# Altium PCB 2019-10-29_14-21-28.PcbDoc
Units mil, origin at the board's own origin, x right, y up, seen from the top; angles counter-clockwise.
Board outline 2004 x 2504 mil, 4 copper layers (Top Layer, MidLayer1, MidLayer2, Bottom Layer); 21 components, 11 nets, 42 pads, 203 vias.
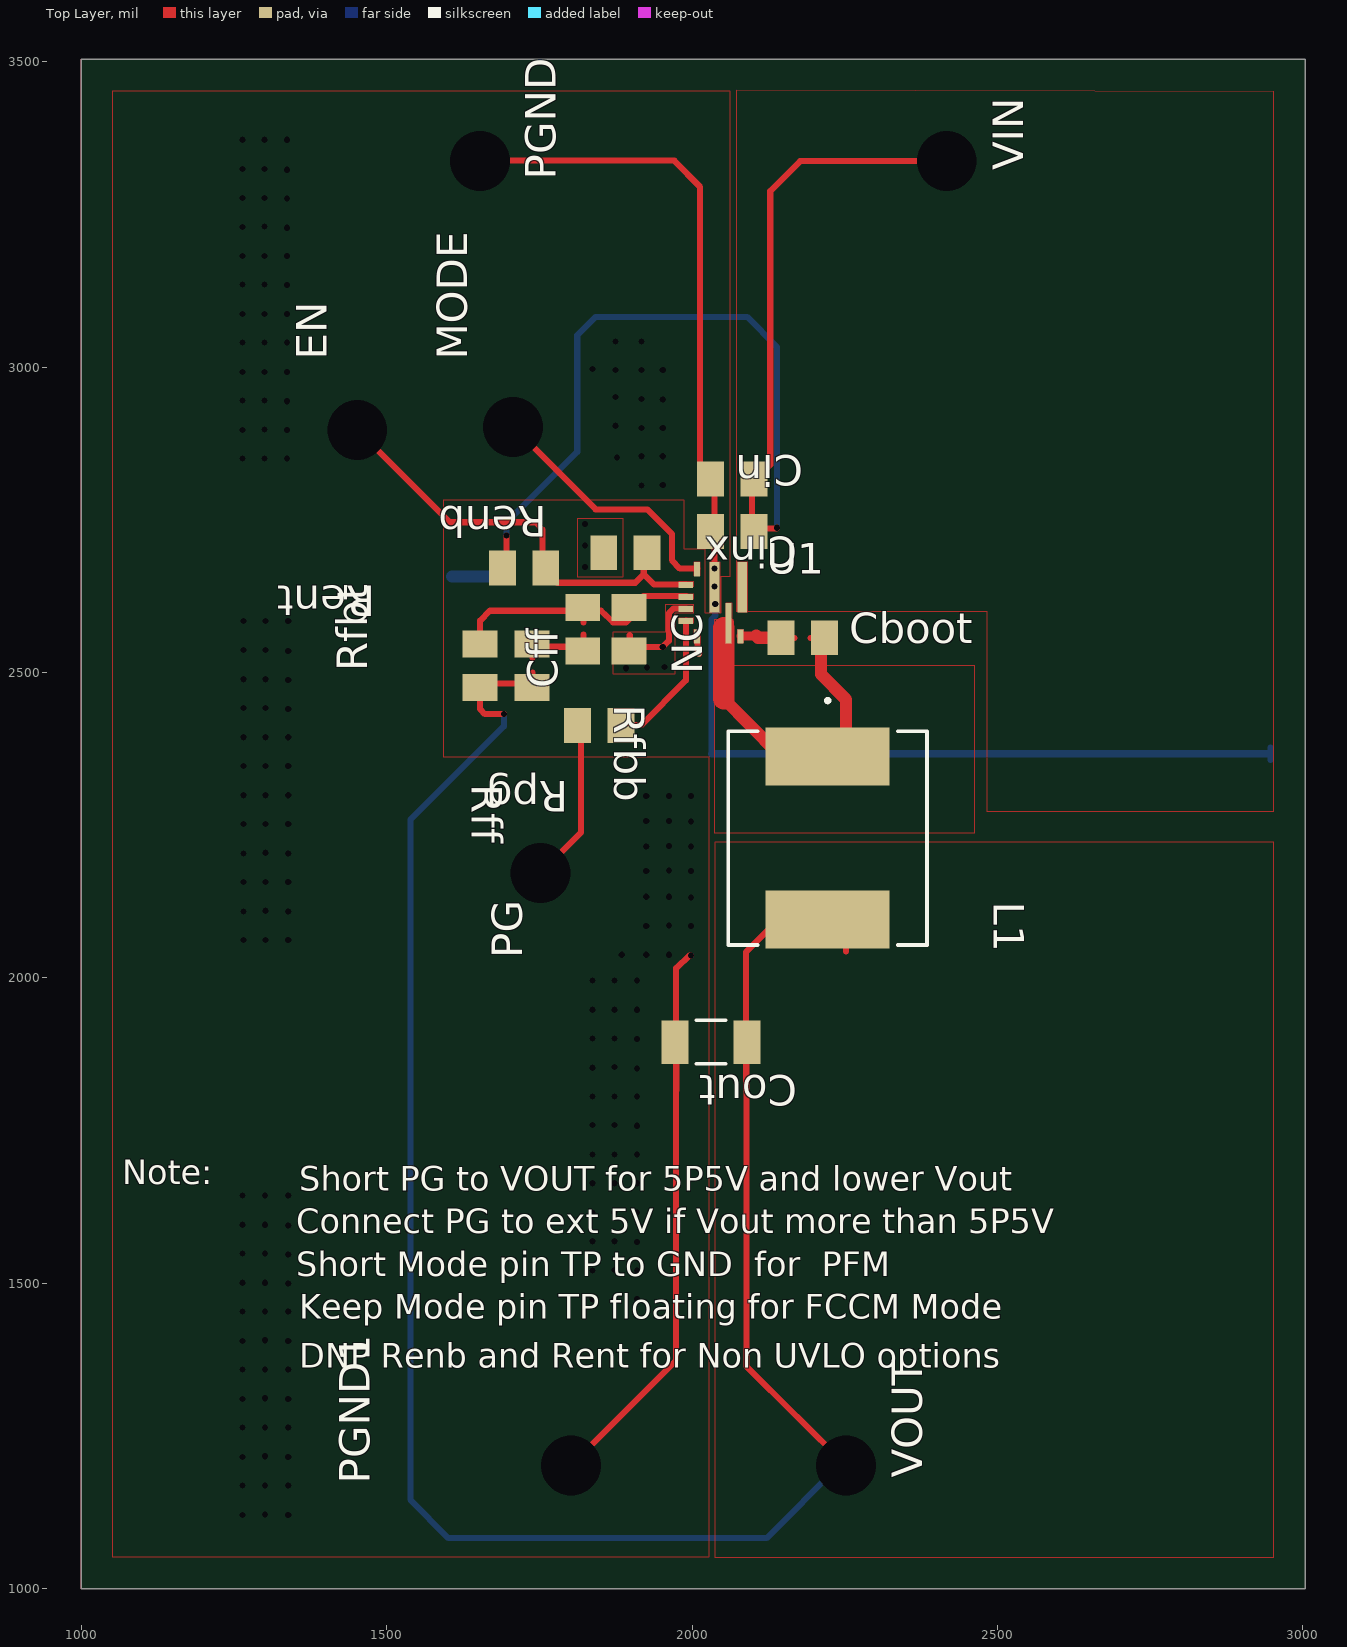
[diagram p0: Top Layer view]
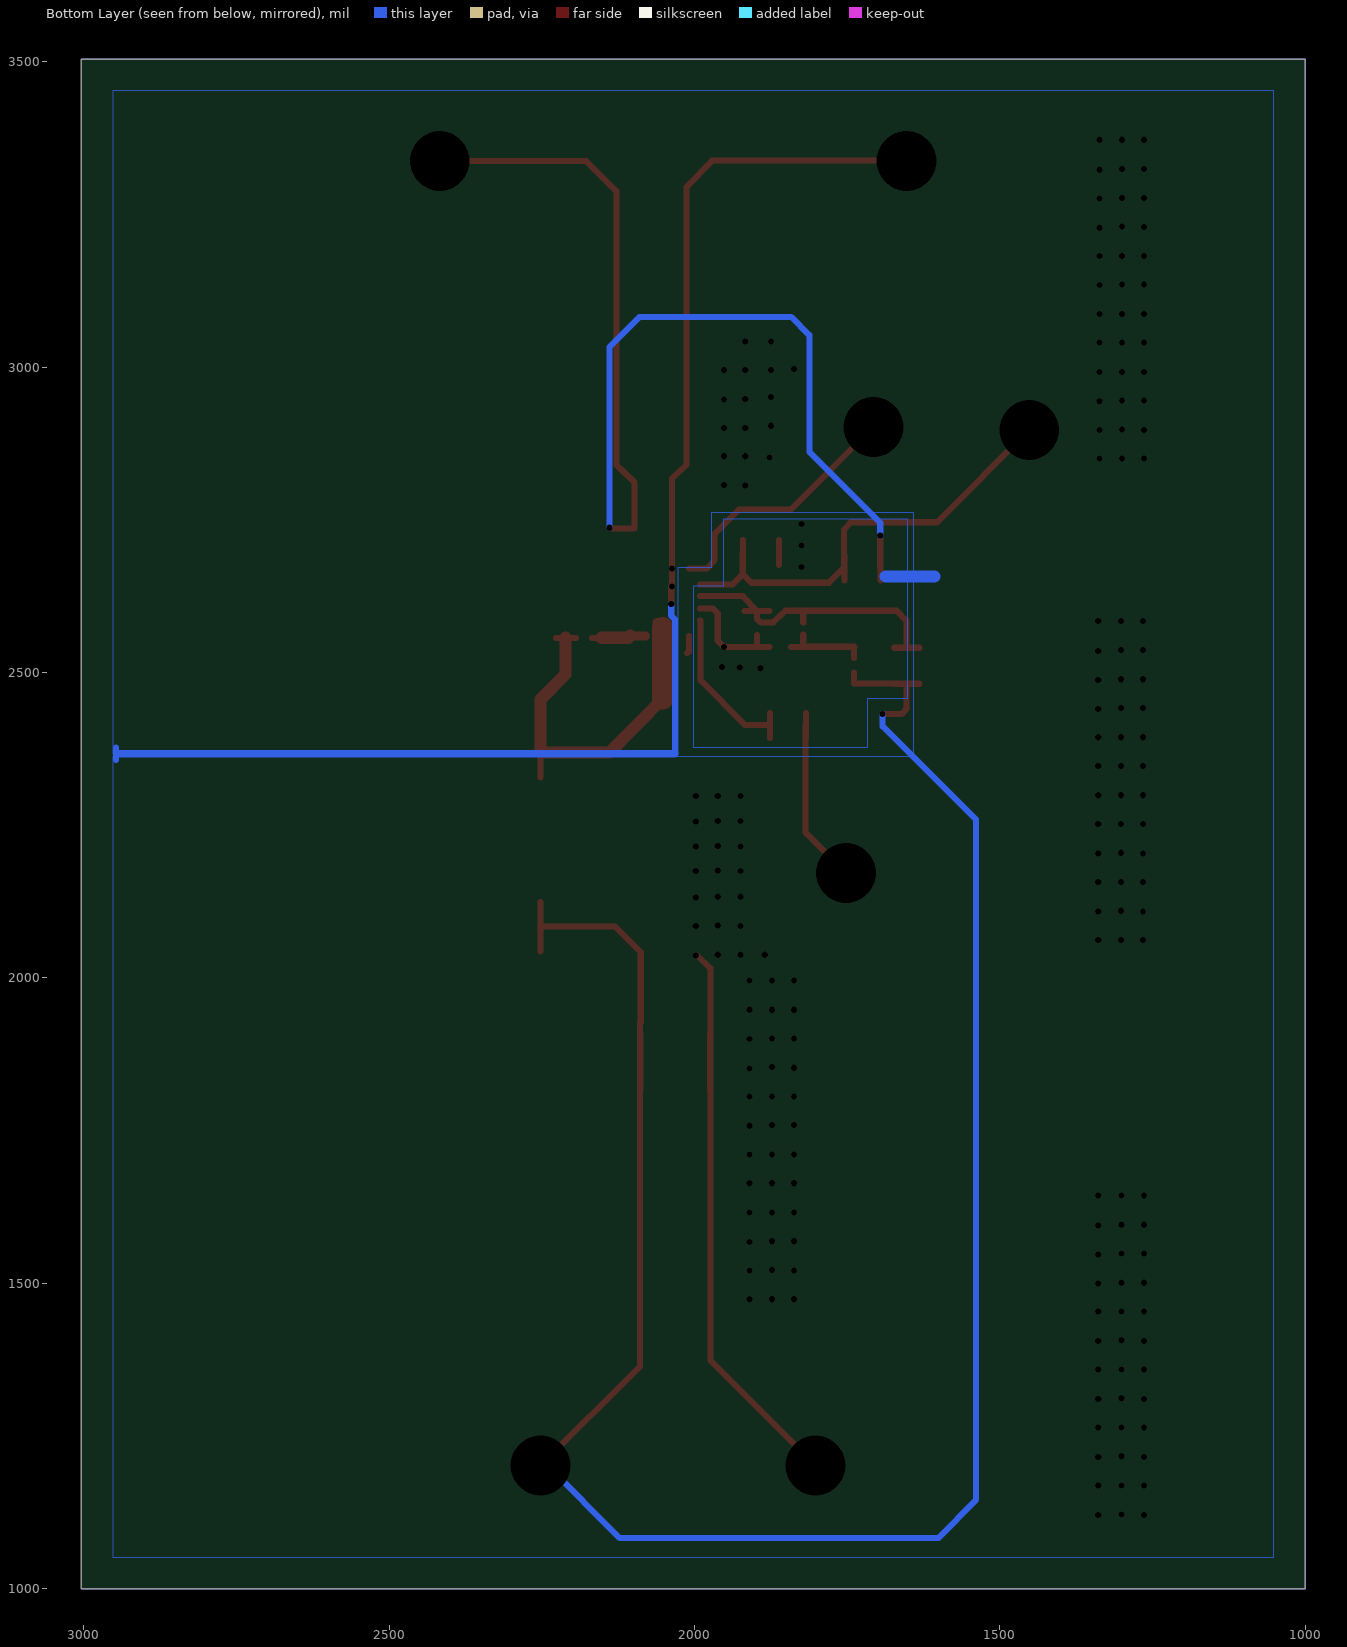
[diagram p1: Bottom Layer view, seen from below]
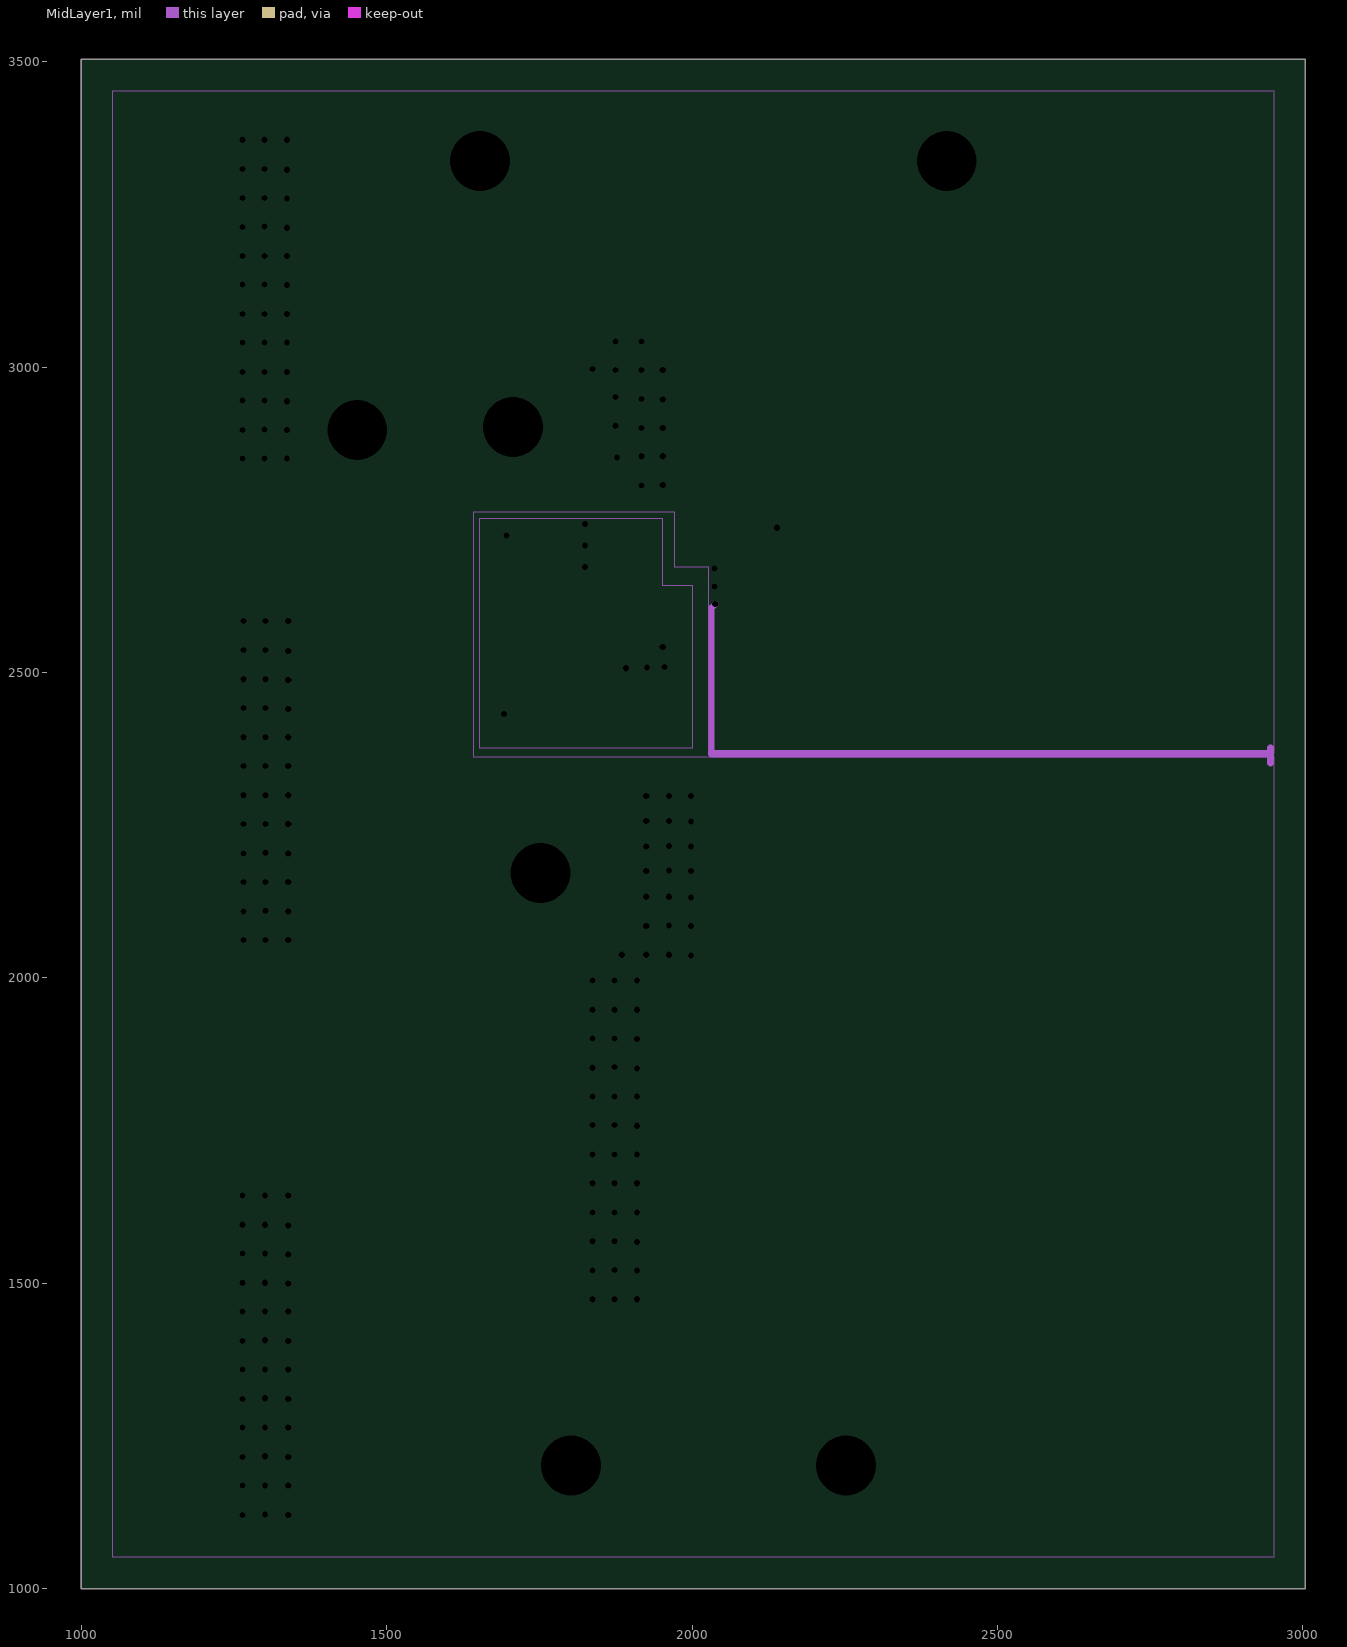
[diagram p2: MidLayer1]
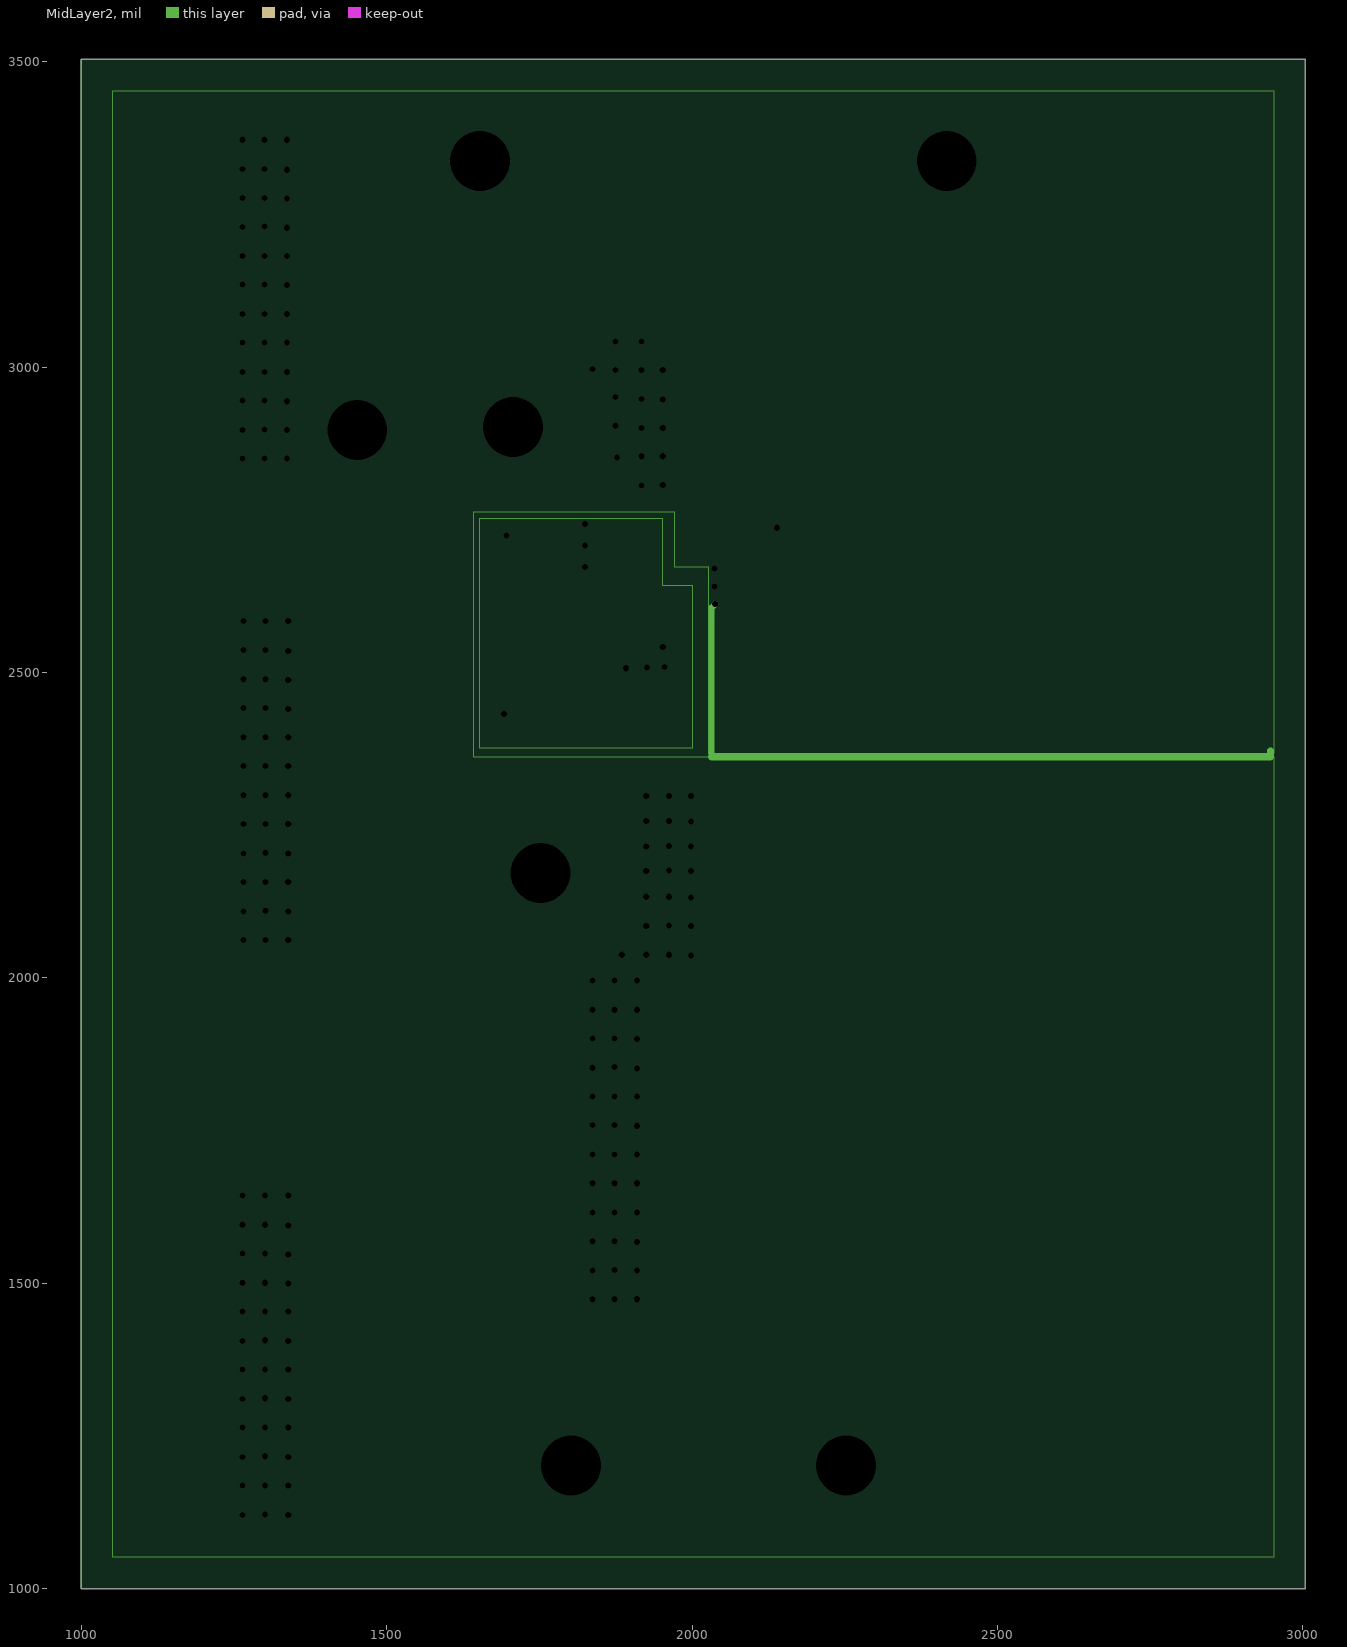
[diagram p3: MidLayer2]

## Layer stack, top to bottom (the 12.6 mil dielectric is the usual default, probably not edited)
Top Layer: signal copper 1.4
Dielectric: core 12.6, FR-4, Dk 4.8
MidLayer1: signal copper 1.4
Dielectric: prepreg 12.6, FR-4, Dk 4.8
MidLayer2: signal copper 1.4
Dielectric: core 12.6, FR-4, Dk 4.8
Bottom Layer: signal copper 1.4

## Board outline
1000,1000 3004,1000 3004,3504 1000,3504

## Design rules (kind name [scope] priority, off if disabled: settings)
PlaneConnect [All] p0: scope1count=1 scope1_0_kind=Board scope1_0_value=Board scope2count=1 scope2_0_kind=Board scope2_0_value=Board commentlength=0 planeconnectstyle=Direct reliefexpansion=20 reliefentries=4 reliefconductorwidth=10 reliefairgap=10
PlaneConnect [All] p1: planeconnectstyle=Direct reliefexpansion=20 reliefentries=4 reliefconductorwidth=10 reliefairgap=10
PolygonConnect [All] p0: scope1count=1 scope1_0_kind=Board scope1_0_value=Board scope2count=1 scope2_0_kind=Board scope2_0_value=Board commentlength=0 connectstyle=Direct reliefconductorwidth=10 reliefentries=4 polygonreliefangle="90 Angle"
PolygonConnect [All] p1: connectstyle=Direct reliefconductorwidth=10 reliefentries=4 polygonreliefangle="90 Angle"

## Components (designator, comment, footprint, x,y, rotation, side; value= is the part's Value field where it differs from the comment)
Cboot "" 0805 2181,2557 r0 top
Cff "" 0805 1821,2571 r90 top
Cin "" 0805 2066,2817 r180 top
Cinx "" 0805 2066,2731 r180 top
Cout "" 1206_190 2031,1895 r180 top
EN "" TP-1502 1451,2896 r90 top
L1 "" IHLP-3232DZ 2222,2229 r270 top
MODE "" TP-1502 1706,2901 r90 top
NC "" SMD_PAD1 2011,2531 r90 top
PG "" TP-1502 1751,2171 r90 top
PGND "" TP-1502 1653,3336 r90 top
PGND1 "" TP-1502 1801,1201 r90 top
Renb "" 0805 1891,2696 r180 top
Rent "" 0805 1725,2671 r180 top
Rfbb "" 0805 1897,2571 r270 top
Rfbt "" 0805 1653,2511 r90 top
Rff "" 0805 1738,2511 r270 top
Rpg "" 0805 1848,2413 r180 top
U1 "" RPA0010A 2045,2614 r0 top
VIN "" TP-1502 2416,3336 r90 top
VOUT "" TP-1502 2251,1201 r90 top

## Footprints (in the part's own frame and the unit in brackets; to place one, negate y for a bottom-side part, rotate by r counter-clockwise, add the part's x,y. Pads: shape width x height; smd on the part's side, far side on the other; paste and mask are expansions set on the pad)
0805 [mil]
  rect 44x57 smd: 1(-35.5,0) 2(35.5,0)
1206_190 [mil]
  rect 44x71 smd: 1(-59,0) 2(59,0)
  silkscreen extent -24,-36 24,36
IHLP-3232DZ [mil]
  rect 95x203 smd: 1(-133.5,0) 2(133.5,0)
  silkscreen extent -228,-163 175,163
RPA0010A [mm]
  rect 0.6x0.25 smd: 1(-1.4,0.75) 2(-1.4,0.25) 3(-1.4,-0.25) 4(-1.4,-0.75)
  rect 0.25x0.6 smd: 5(-0.93,-1.4) 7(0.87,-1.4) 10(-0.93,1.4)
  rect 0.25x1.7 smd: 6(0.37,-0.85)
  rect 0.4x2.1 smd: 8(0.95,0.65) 9(-0.21,0.65)
SMD_PAD1 [mil]
  round 10 smd: 1(0,0)
TP-1502 [mil]
  round 65 / inner round 0 / far side round 65 hole 32: 1(0,0)

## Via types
v1: diameter 0, hole 10, Top Layer to Bottom Layer, 196 vias
v2: diameter 0, hole 98, Top Layer to Bottom Layer, 7 vias

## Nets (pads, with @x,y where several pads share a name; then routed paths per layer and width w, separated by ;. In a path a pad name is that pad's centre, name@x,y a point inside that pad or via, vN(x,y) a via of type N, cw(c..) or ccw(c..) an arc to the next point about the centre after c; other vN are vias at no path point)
0: Cin.2 Cinx.2 Cout.2 PGND1.1 PGND.1 Renb.2 Rfbb.2 U1.3 U1.9 | length 5945.9
  Top Layer w10: PGND.1@1653,3338 1971,3338 2013,3295 2013,2840 2037,2817 2037,2732 v1(2037,2670) v1(2037,2641) 2038,2641 v1(2038,2612) ; v2(1802,1202) 1974,1374 1974,1862 1974,2016 1996,2037 v1(1998,2037) ; Renb.2@1861.5,2676 Renb.2@1861.5,2717 ; Rfbb.2@1877,2541.5 Rfbb.2@1918,2541.5 ; 1898,2561 1898,2542 v1(1952,2542) 1962,2552 1962,2597 1970,2605 U1.3@1991,2605 ; 1974.5,1816 Cout.2@1974.5,1908
  MidLayer1 w10: 2032,2367 2032,2606 v1(2038,2612)
  MidLayer1 w11: 2947,2352 2947,2377
  MidLayer1 w12: 2032,2367 2942,2367
  MidLayer2 w10: 2032,2362 2032,2606 v1(2038,2612)
  MidLayer2 w11: 2947,2362 2947,2372
  MidLayer2 w12: 2032,2362 2947,2362
  Bottom Layer w10: 2032,2367 2032,2587 2038,2593 v1(2038,2612) ; 2947,2357 2947,2377
  Bottom Layer w12: 2032,2367 2942,2367
  Bottom Layer w20: 1607,2657 1687,2657
  other v1: 1264,1121 1339,1121 1301,1122 1264,1169 1301,1169 1339,1169 1264,1216 1339,1216 1301,1217 1264,1264 1301,1264 1339,1264 1264,1311 1339,1311 1301,1312 1264,1359 1301,1359 1339,1359 1264,1406 1339,1406 1301,1407 1264,1454 1301,1454 1339,1454 1837,1474 1873,1474 1910,1474 1339,1500 1264,1501 1301,1501 1837,1521 1910,1521 1873,1522 1339,1547 1264,1549 1301,1549 1910,1568 1837,1569 1873,1569 1339,1595 1264,1596 1301,1596 1837,1616 1873,1616 1910,1616 1264,1644 1301,1644 1339,1644 1837,1664 1873,1664 1910,1664 1837,1711 1873,1711 1910,1711 1910,1758 1837,1759 1873,1759 1837,1806 1873,1806 1910,1806 1910,1852 1837,1853 1873,1854 1910,1900 1837,1901 1873,1901 1837,1948 1873,1948 1910,1948 1837,1996 1873,1996 1910,1996 1885,2038 1925,2038 1962,2038 1266,2062 1302,2062 1339,2062 1925,2085 1998,2085 1962,2086 1266,2109 1339,2109 1302,2110 1998,2132 1925,2133 1962,2133 1266,2157 1302,2157 1339,2157 1925,2175 1998,2175 1962,2176 1266,2204 1339,2204 1302,2205 1925,2215 1998,2215 1962,2216 1266,2252 1302,2252 1339,2252 1998,2256 1925,2257 1962,2257 1925,2298 1962,2298 1998,2298 1266,2299 1302,2299 1339,2299 1266,2347 1302,2347 1339,2347 1266,2394 1302,2394 1339,2394 1339,2440 1266,2442 1302,2442 1339,2488 1266,2489 1302,2489 1892,2507 1926,2508 1955,2509 1339,2535 1266,2537 1302,2537 1266,2584 1302,2584 1339,2584 1825,2673 1825,2708 1825,2743 1917,2806 1952,2807 1264,2850 1300,2850 1337,2850 1877,2852 1917,2854 1952,2854 1264,2897 1337,2897 1300,2898 1917,2900 1952,2900 1875,2904 1337,2944 1264,2945 1300,2945 1952,2947 1917,2948 1875,2951 1264,2992 1300,2992 1337,2992 1875,2995 1917,2995 1952,2995 1837,2997 1264,3040 1300,3040 1337,3040 1875,3042 1917,3042 1264,3087 1300,3087 1337,3087 1337,3134 1264,3135 1300,3135 1264,3182 1300,3182 1337,3182 1337,3228 1264,3229 1300,3230 1337,3276 1264,3277 1300,3277 1337,3323 1264,3324 1300,3324 1264,3372 1300,3372 1337,3372
  other v2: 1653,3337
1: Cff.2 Rfbb.1 Rfbt.2 U1.2 | length 563.9
  Top Layer w10: Rfbt.2@1632,2540.5 Rfbt.2@1673,2540.5 ; Rfbt.2@1653,2541 1653,2585 1669,2601 Cff.2@1822,2601 ; Cff.2@1801,2600.5 Cff.2@1842,2600.5 ; 1822,2582 Cff.2@1822,2601 ; Rfbb.1@1877,2600.5 Rfbb.1@1918,2600.5 ; U1.2@1991,2625 1921,2625 1898,2601 1898,2588 1892,2582 1871,2582 1851,2601 Cff.2@1822,2601
2: Cout.1 L1.2 PG.1 Rfbt.1 Rff.2 Rpg.2 VOUT.1 | length 3939.9
  Top Layer w10: Rfbt.1@1632,2481.5 Rfbt.1@1673,2481.5 ; v1(1692,2432) 1661,2432 1653,2440 1653,2482 1739,2482 1739,2500 ; v2(1752,2172) 1818,2238 Rpg.2@1818,2414 ; Rpg.2@1817.5,2393 Rpg.2@1817.5,2434 ; Cout.1@2088,1926 2088,2042 2130,2084 L1.2@2252,2084 ; 2088.5,1816 Cout.1@2088.5,1908 ; Cout.1@2089,1926 2089,1862 2089,1364 v2(2252,1202) ; 2252,2043 L1.2@2252,2124
  Bottom Layer w10: v1(1692,2432) 1692,2412 1539,2259 1539,1146 1601,1083 2122,1083 2241,1202 v2(2252,1202)
3: Cff.1 Rff.1 | length 162
  Top Layer w10: 1739,2524 Rff.1@1739,2541 ; Cff.1@1801,2541.5 Cff.1@1842,2541.5 ; Cff.1@1822,2542 1822,2562
  Top Layer w11: Rff.1@1739,2541 1739,2542 Cff.1@1822,2542
5: Cboot.2 L1.1 U1.6 | length 684.5
  Top Layer w10: 2194,2556.5 Cboot.2@2227,2556.5 ; L1.1@2252,2328 L1.1@2252,2409
  Top Layer w15: 2052,2573 U1.6@2061,2582
  Top Layer w20: 2052,2457 2139,2369 2252,2369 2252,2456 2211,2497 Cboot.2@2211,2557
  Top Layer w35: 2052,2457 2052,2573
6: Cin.1 Cinx.1 Rent.2 U1.8 VIN.1 | length 2040.2
  Top Layer w10: Rent.2@1695.5,2651 Rent.2@1695.5,2692 ; Rent.2@1696,2672 v1(1696,2724) ; v1(2139,2737) 2138,2736 2098,2736 2098,2811 2128,2840 2128,3288 2177,3337 v2(2417,3337)
  Bottom Layer w10: v1(1696,2724) 1696,2745 1812,2861 1812,3052 1842,3082 2090,3082 2139,3033 v1(2139,2737)
10: EN.1 Renb.1 Rent.1 U1.1 | length 810
  Top Layer w10: v2(1452,2897) 1603,2746 1744,2746 1755,2734 1755,2672 1780,2647 1907,2647 1921,2661 ; Rent.1@1754.5,2651 Rent.1@1754.5,2692 ; Renb.1@1920.5,2676 Renb.1@1920.5,2717 ; Renb.1@1921,2697 1921,2661 ; U1.1@1991,2644 1938,2644 1921,2661
16: Cboot.1 U1.7 | length 106.2
  Top Layer w10: Cboot.1@2135,2556.5 2168,2556.5
  Top Layer w15: U1.7@2080,2560 2105,2560
  Top Layer w20: 2105,2560 2108,2557 Cboot.1@2152,2557
17: Rpg.1 U1.4 | length 281.2
  Top Layer w10: Rpg.1@1876.5,2393 Rpg.1@1876.5,2434 ; Rpg.1@1879,2414 1917,2414 1990,2487 1990,2585 U1.4@1991,2585
18: MODE.1 U1.10 | length 423.6
  Top Layer w10: v2(1707,2902) 1842,2767 1927,2767 1967,2727 1967,2684 1980,2670 U1.10@2009,2670
19: NC.1 U1.5 | length 29.6
  Top Layer w10: U1.5@2009,2560 2009,2534 NC.1@2012,2532

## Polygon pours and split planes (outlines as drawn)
10 on Top Layer " " (solid, pour order 0): 1979,2640 1979,2649 2002,2649 2002,2640
1 on Top Layer " " (solid, pour order 1): 1979,2620 1979,2629 2002,2629 2002,2620
17 on Top Layer " " (solid, pour order 2): 1979,2581 1979,2590 2002,2590 2002,2581
19 on Top Layer " " (solid, pour order 3): 2004,2548 2004,2571 2013,2571 2013,2548
5 on Top Layer " " (solid, pour order 4): 2056,2548 2056,2614 2065,2614 2065,2548
16 on Top Layer " " (solid, pour order 5): 2075,2548 2075,2571 2084,2571 2084,2548
6 on Top Layer " " (solid, pour order 6): 2075,2599 2075,2681 2090,2681 2090,2599
18 on Top Layer " " (solid, pour order 7): 2004,2658 2004,2681 2013,2681 2013,2658
19 on Top Layer " " (solid, pour order 8): 2017,2532 2016,2532 2016,2533 2016,2534 2015,2535 2014,2536 2013,2536 2012,2536 2012,2537 2011,2536 2010,2536 2009,2536 2008,2535 2007,2534 2007,2533 2007,2532 2007,2531 2007,2530 2007,2529 2008,2528 2009,2527 2010,2527 2011,2527 2012,2527 2013,2527 2014,2527 2015,2528 2016,2529 2016,2530 2016,2531 2017,2532
6 on Top Layer " " (solid, pour order 9): 2072,3453 2072,2600 2482,2600 2482,2273 2952,2273 2952,3451
2 on Top Layer " " (solid, pour order 10): 2952,2222 2037,2222 2037,1052 2952,1052
5 on Top Layer " " (solid, pour order 11): 2067,2587 2067,2512 2462,2512 2462,2237 2037,2237 2037,2587
0 on Top Layer " " (solid, pour order 12): 1979,2600 1979,2609 2002,2609 2002,2600
0 on Top Layer " " (solid, pour order 13): 2030,2599 2030,2681 2045,2681 2045,2599
0 on Top Layer " " (solid, pour order 20): 2047,2657 2047,2597 2022,2597 2022,2702 1987,2702 1987,2782 1593,2782 1593,2362 2027,2362 2027,1052 1052,1052 1052,3452 2062,3452 2062,2657
0 on Top Layer " " (solid, pour order 21): 1887,2752 1812,2752 1812,2657 1887,2657
0 on Top Layer " " (solid, pour order 22): 1972,2597 1972,2497 1871,2497 1871,2567 1957,2567 1957,2612 2002,2612 2002,2597
0 on Bottom Layer " " (solid, pour order 18): 1652,2457 1717,2457 1717,2377 2001,2377 2001,2572 2001,2642 1952,2642 1952,2752 1652,2752
0 on Bottom Layer " " (solid, pour order 19): 2952,2367 2027,2367 2027,2672 1972,2672 1972,2762 1642,2762 1642,2362 2952,2362 2952,1052 1052,1052 1052,3452 2952,3452
0 on MidLayer1 " " (solid, pour order 14): 2001,2642 1952,2642 1952,2752 1652,2752 1652,2377 2001,2377 2001,2572
0 on MidLayer1 " " (solid, pour order 15): 2952,2367 2027,2367 2027,2672 1972,2672 1972,2762 1642,2762 1642,2362 2952,2362 2952,1052 1052,1052 1052,3452 2952,3452
0 on MidLayer2 " " (solid, pour order 16): 2001,2642 1952,2642 1952,2752 1652,2752 1652,2377 2001,2377 2001,2572
0 on MidLayer2 " " (solid, pour order 17): 2952,2367 2027,2367 2027,2672 1972,2672 1972,2762 1642,2762 1642,2362 2952,2362 2952,1052 1052,1052 1052,3452 2952,3452

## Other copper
Multi-Layer:
  the board outline again, w1

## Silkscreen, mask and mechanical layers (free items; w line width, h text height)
Top Overlay:
  text "Note:" at 1067,1662 h40
  text "Short PG to VOUT for 5P5V and lower Vout" at 1357,1652 h40
  text "Connect PG to ext 5V if Vout more than 5P5V" at 1352,1582 h40
  text "Short Mode pin TP to GND  for  PFM" at 1352,1512 h40
  text "Keep Mode pin TP floating for FCCM Mode" at 1357,1442 h40
  text "DNP Renb and Rent for Non UVLO options" at 1357,1362 h40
